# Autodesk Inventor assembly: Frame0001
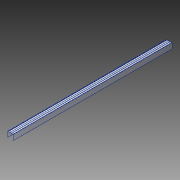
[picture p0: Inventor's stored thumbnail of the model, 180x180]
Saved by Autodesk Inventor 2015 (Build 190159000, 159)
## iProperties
Created: 2015-04
Part Number: Frame0001
Document SubType Name: Assembly
Designer: suporte
_FrameDoc: Frame Assembly
_Version: 15.0.0
Author: suporte
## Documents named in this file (94)
- C:\Users\suporte\Desktop\Kévin\WorldSkills SP\Grupo Kazuo\21\Arquivos Edição\Arquivos Inventor\Drywall\Frame\Frame0001.iam
- C:\Users\suporte\Desktop\Kévin\WorldSkills SP\Grupo Kazuo\21\Arquivos Edição\Arquivos Inventor\Drywall\Frame\Skeleton0001.ipt
- C:\Users\suporte\Desktop\Kévin\WorldSkills SP\Grupo Kazuo\21\Arquivos Edição\Arquivos Inventor\Drywall\Frame\Kevin  00000005.ipt
- Kevin  00000005.ipt
- C:\Users\suporte\Desktop\Kévin\WorldSkills SP\Grupo Kazuo\21\Arquivos Edição\Arquivos Inventor\Drywall\Frame\Kevin  00000006.ipt
- Kevin  00000006.ipt
- C:\Users\suporte\Desktop\Kévin\WorldSkills SP\Grupo Kazuo\21\Arquivos Edição\Arquivos Inventor\Drywall\Frame\Kevin  00000007.ipt
- Kevin  00000007.ipt
- C:\Users\suporte\Desktop\Kévin\WorldSkills SP\Grupo Kazuo\21\Arquivos Edição\Arquivos Inventor\Drywall\Frame\Kevin  00000008.ipt
- Kevin  00000008.ipt
- C:\Users\suporte\Desktop\Kévin\WorldSkills SP\Grupo Kazuo\21\Arquivos Edição\Arquivos Inventor\Drywall\Frame\Kevin  00000036.ipt
- Kevin  00000036.ipt
- C:\Users\suporte\Desktop\Kévin\WorldSkills SP\Grupo Kazuo\21\Arquivos Edição\Arquivos Inventor\Drywall\Frame\Kevin  00000037.ipt
- Kevin  00000037.ipt
- C:\Users\suporte\Desktop\Kévin\WorldSkills SP\Grupo Kazuo\21\Arquivos Edição\Arquivos Inventor\Drywall\Frame\Kevin  00000038.ipt
- Kevin  00000038.ipt
- C:\Users\suporte\Desktop\Kévin\WorldSkills SP\Grupo Kazuo\21\Arquivos Edição\Arquivos Inventor\Drywall\Frame\Kevin  00000039.ipt
- Kevin  00000039.ipt
- C:\Users\suporte\Desktop\Kévin\WorldSkills SP\Grupo Kazuo\21\Arquivos Edição\Arquivos Inventor\Drywall\Frame\Kevin  00000040.ipt
- Kevin  00000040.ipt
- C:\Users\suporte\Desktop\Kévin\WorldSkills SP\Grupo Kazuo\21\Arquivos Edição\Arquivos Inventor\Drywall\Frame\Kevin  00000041.ipt
- Kevin  00000041.ipt
- C:\Users\suporte\Desktop\Kévin\WorldSkills SP\Grupo Kazuo\21\Arquivos Edição\Arquivos Inventor\Drywall\Frame\Kevin  00000042.ipt
- Kevin  00000042.ipt
- C:\Users\suporte\Desktop\Kévin\WorldSkills SP\Grupo Kazuo\21\Arquivos Edição\Arquivos Inventor\Drywall\Frame\Kevin  00000043.ipt
- Kevin  00000043.ipt
- C:\Users\suporte\Desktop\Kévin\WorldSkills SP\Grupo Kazuo\21\Arquivos Edição\Arquivos Inventor\Drywall\Frame\Kevin  00000044.ipt
- Kevin  00000044.ipt
- C:\Users\suporte\Desktop\Kévin\WorldSkills SP\Grupo Kazuo\21\Arquivos Edição\Arquivos Inventor\Drywall\Frame\Kevin  00000045.ipt
- Kevin  00000045.ipt
- C:\Users\suporte\Desktop\Kévin\WorldSkills SP\Grupo Kazuo\21\Arquivos Edição\Arquivos Inventor\Drywall\Frame\Kevin  00000046.ipt
- Kevin  00000046.ipt
- C:\Users\suporte\Desktop\Kévin\WorldSkills SP\Grupo Kazuo\21\Arquivos Edição\Arquivos Inventor\Drywall\Frame\Kevin  00000047.ipt
- Kevin  00000047.ipt
- C:\Users\suporte\Desktop\Kévin\WorldSkills SP\Grupo Kazuo\21\Arquivos Edição\Arquivos Inventor\Drywall\Frame\Kevin  00000048.ipt
- Kevin  00000048.ipt
- C:\Users\suporte\Desktop\Kévin\WorldSkills SP\Grupo Kazuo\21\Arquivos Edição\Arquivos Inventor\Drywall\Frame\Kevin  00000049.ipt
- Kevin  00000049.ipt
- C:\Users\suporte\Desktop\Kévin\WorldSkills SP\Grupo Kazuo\21\Arquivos Edição\Arquivos Inventor\Drywall\Frame\Kevin  00000050.ipt
- Kevin  00000050.ipt
- C:\Users\suporte\Desktop\Kévin\WorldSkills SP\Grupo Kazuo\21\Arquivos Edição\Arquivos Inventor\Drywall\Frame\Kevin  00000051.ipt
- Kevin  00000051.ipt
- C:\Users\suporte\Desktop\Kévin\WorldSkills SP\Grupo Kazuo\21\Arquivos Edição\Arquivos Inventor\Drywall\Frame\Kevin  00000052.ipt
- Kevin  00000052.ipt
- C:\Users\suporte\Desktop\Kévin\WorldSkills SP\Grupo Kazuo\21\Arquivos Edição\Arquivos Inventor\Drywall\Frame\Kevin  00000053.ipt
- Kevin  00000053.ipt
- C:\Users\suporte\Desktop\Kévin\WorldSkills SP\Grupo Kazuo\21\Arquivos Edição\Arquivos Inventor\Drywall\Frame\Kevin  00000054.ipt
- Kevin  00000054.ipt
- C:\Users\suporte\Desktop\Kévin\WorldSkills SP\Grupo Kazuo\21\Arquivos Edição\Arquivos Inventor\Drywall\Frame\Kevin  00000055.ipt
- Kevin  00000055.ipt
- C:\Users\suporte\Desktop\Kévin\WorldSkills SP\Grupo Kazuo\21\Arquivos Edição\Arquivos Inventor\Drywall\Frame\Kevin  00000056.ipt
- Kevin  00000056.ipt
- C:\Users\suporte\Desktop\Kévin\WorldSkills SP\Grupo Kazuo\21\Arquivos Edição\Arquivos Inventor\Drywall\Frame\Kevin  00000057.ipt
- Kevin  00000057.ipt
- C:\Users\suporte\Desktop\Kévin\WorldSkills SP\Grupo Kazuo\21\Arquivos Edição\Arquivos Inventor\Drywall\Frame\Kevin  00000058.ipt
- Kevin  00000058.ipt
- C:\Users\suporte\Desktop\Kévin\WorldSkills SP\Grupo Kazuo\21\Arquivos Edição\Arquivos Inventor\Drywall\Frame\Kevin  00000059.ipt
- Kevin  00000059.ipt
- C:\Users\suporte\Desktop\Kévin\WorldSkills SP\Grupo Kazuo\21\Arquivos Edição\Arquivos Inventor\Drywall\Frame\Kevin  00000060.ipt
- Kevin  00000060.ipt
- C:\Users\suporte\Desktop\Kévin\WorldSkills SP\Grupo Kazuo\21\Arquivos Edição\Arquivos Inventor\Drywall\Frame\Kevin  00000061.ipt
- Kevin  00000061.ipt
- C:\Users\suporte\Desktop\Kévin\WorldSkills SP\Grupo Kazuo\21\Arquivos Edição\Arquivos Inventor\Drywall\Frame\Kevin  00000062.ipt
- Kevin  00000062.ipt
- C:\Users\suporte\Desktop\Kévin\WorldSkills SP\Grupo Kazuo\21\Arquivos Edição\Arquivos Inventor\Drywall\Frame\Kevin  00000063.ipt
- Kevin  00000063.ipt
- C:\Users\suporte\Desktop\Kévin\WorldSkills SP\Grupo Kazuo\21\Arquivos Edição\Arquivos Inventor\Drywall\Frame\Kevin  00000064.ipt
- Kevin  00000064.ipt
- C:\Users\suporte\Desktop\Kévin\WorldSkills SP\Grupo Kazuo\21\Arquivos Edição\Arquivos Inventor\Drywall\Frame\Kevin  00000065.ipt
- Kevin  00000065.ipt
- C:\Users\suporte\Desktop\Kévin\WorldSkills SP\Grupo Kazuo\21\Arquivos Edição\Arquivos Inventor\Drywall\Frame\Kevin  00000066.ipt
- Kevin  00000066.ipt
- C:\Users\suporte\Desktop\Kévin\WorldSkills SP\Grupo Kazuo\21\Arquivos Edição\Arquivos Inventor\Drywall\Frame\Kevin  00000067.ipt
- Kevin  00000067.ipt
- C:\Users\suporte\Desktop\Kévin\WorldSkills SP\Grupo Kazuo\21\Arquivos Edição\Arquivos Inventor\Drywall\Frame\Kevin  00000068.ipt
- Kevin  00000068.ipt
- C:\Users\suporte\Desktop\Kévin\WorldSkills SP\Grupo Kazuo\21\Arquivos Edição\Arquivos Inventor\Drywall\Frame\Kevin  00000069.ipt
- Kevin  00000069.ipt
- C:\Users\suporte\Desktop\Kévin\WorldSkills SP\Grupo Kazuo\21\Arquivos Edição\Arquivos Inventor\Drywall\Frame\Kevin  00000070.ipt
- Kevin  00000070.ipt
- C:\Users\suporte\Desktop\Kévin\WorldSkills SP\Grupo Kazuo\21\Arquivos Edição\Arquivos Inventor\Drywall\Frame\Kevin  00000071.ipt
- Kevin  00000071.ipt
- C:\Users\suporte\Desktop\Kévin\WorldSkills SP\Grupo Kazuo\21\Arquivos Edição\Arquivos Inventor\Drywall\Frame\Kevin  00000072.ipt
- Kevin  00000072.ipt
- C:\Users\suporte\Desktop\Kévin\WorldSkills SP\Grupo Kazuo\21\Arquivos Edição\Arquivos Inventor\Drywall\Frame\Kevin  00000073.ipt
- Kevin  00000073.ipt
- C:\Users\suporte\Desktop\Kévin\WorldSkills SP\Grupo Kazuo\21\Arquivos Edição\Arquivos Inventor\Drywall\Frame\Kevin  00000074.ipt
- Kevin  00000074.ipt
- C:\Users\suporte\Desktop\Kévin\WorldSkills SP\Grupo Kazuo\21\Arquivos Edição\Arquivos Inventor\Drywall\Frame\Kevin  00000075.ipt
- Kevin  00000075.ipt
- C:\Users\suporte\Desktop\Kévin\WorldSkills SP\Grupo Kazuo\21\Arquivos Edição\Arquivos Inventor\Drywall\Frame\Kevin  00000076.ipt
- Kevin  00000076.ipt
- C:\Users\suporte\Desktop\Kévin\WorldSkills SP\Grupo Kazuo\21\Arquivos Edição\Arquivos Inventor\Drywall\Frame\Kevin  00000077.ipt
- Kevin  00000077.ipt
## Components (47 placed, 47 different names)
1. Frame Reference Model
2. Kevin  00000005:1
3. Kevin  00000006:1
4. Kevin  00000007:1
5. Kevin  00000008:1
6. Kevin  00000036:1
7. Kevin  00000037:1
8. Kevin  00000038:1
9. Kevin  00000039:1
10. Kevin  00000040:1
11. Kevin  00000041:1
12. Kevin  00000042:1
13. Kevin  00000043:1
14. Kevin  00000044:1
15. Kevin  00000045:1
16. Kevin  00000046:1
17. Kevin  00000047:1
18. Kevin  00000048:1
19. Kevin  00000049:1
20. Kevin  00000050:1
21. Kevin  00000051:1
22. Kevin  00000052:1
23. Kevin  00000053:1
24. Kevin  00000054:1
25. Kevin  00000055:1
26. Kevin  00000056:1
27. Kevin  00000057:1
28. Kevin  00000058:1
29. Kevin  00000059:1
30. Kevin  00000060:1
31. Kevin  00000061:1
32. Kevin  00000062:1
33. Kevin  00000063:1
34. Kevin  00000064:1
35. Kevin  00000065:1
36. Kevin  00000066:1
37. Kevin  00000067:1
38. Kevin  00000068:1
39. Kevin  00000069:1
40. Kevin  00000070:1
41. Kevin  00000071:1
42. Kevin  00000072:1
43. Kevin  00000073:1
44. Kevin  00000074:1
45. Kevin  00000075:1
46. Kevin  00000076:1
47. Kevin  00000077:1
